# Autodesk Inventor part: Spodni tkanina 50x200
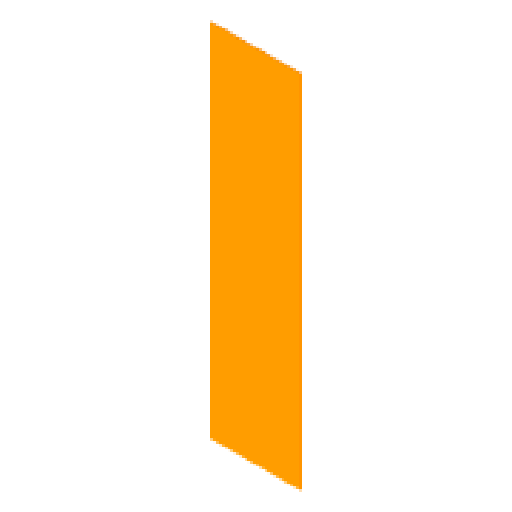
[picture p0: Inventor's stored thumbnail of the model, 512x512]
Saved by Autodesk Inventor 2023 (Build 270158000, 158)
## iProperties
Created: 2025-03
Part Number: Spodni tkanina 50x200
Material: Všeobecné
Document SubType Name: Modeling
Designer: tomik
Density: 1 g/cm^3
Appearance: Výchozí(1)
Author: tomik
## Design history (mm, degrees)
sketch "Náčrt1"
  geometry: L1 (25, -100)-(-25, -100); L2 (-25, -100)-(-25, 100); L3 (-25, 100)-(25, 100); L4 (25, 100)-(25, -100); L5 (25, -100)-(-25, 100); L6 (-25, -100)-(25, 100); 1 further point
  constraints: 12 end point, 2 midpoint, 2 parallel, 1 horizontal, 1 perpendicular
  dimensions: "d0" = 200 distance of L3.end L1.start; "d1" = 50 distance between parallel lines of L2 L4
extrude "Vysunutí1" new body sketch "Náčrt1" distance "d2" = 0.6; taper "d3" = 0 deg
node "Těleso1"
